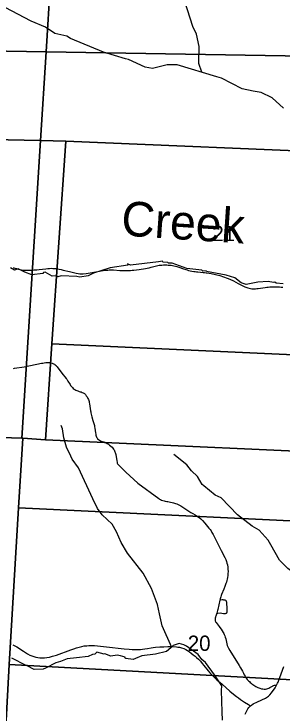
# Model space of a CAD drawing. Extents: x 0 to 34, y 0 to 22.
# Drawn here: x 25.024 to 25.758, y 15.745 to 17.66 of the extents above; entities that cross this region are included whole.
import ezdxf

# ---------------------------------------------------------------- set-up
doc = ezdxf.new("R2010")
doc.units = 0
for name, color, linetype in [('GM_X_County_Road', 7, 'Continuous'), ('GM_X_Minor_River', 7, 'Continuous'), ('GM_X_Minor_River_Text', 7, 'Continuous'), ('GM_X_Section', 7, 'Continuous'), ('GM_X_Section_Text', 7, 'Continuous'), ('GM_X_State_Route', 7, 'Continuous'), ('GM_X_Township_Road', 7, 'Continuous')]:
    doc.layers.add(name, color=color, linetype=linetype)

msp = doc.modelspace()

# ---------------------------------------------------------------- linework, layer by layer
at = {"layer": 'GM_X_County_Road'}
for points in [[(25.328, 16.9572), (25.333, 16.9571), (25.3432, 16.9573), (25.3478, 16.9576), (25.3525, 16.9581), (25.3671, 16.96), (25.3728, 16.9608), (25.3785, 16.9618), (25.3941, 16.9647), (25.3969, 16.9654), (25.4, 16.9662), (25.4145, 16.9699), (25.418, 16.9706), (25.4217, 16.9713), (25.4255, 16.9718), (25.4295, 16.9722), (25.4338, 16.9724), (25.4383, 16.9725), (25.4427, 16.9724), (25.4465, 16.9722), (25.4496, 16.9719), (25.4525, 16.9717), (25.455, 16.9713), (25.4579, 16.9707), (25.4623, 16.9697), (25.4663, 16.9688), (25.4701, 16.9677), (25.4752, 16.9661), (25.4886, 16.9616), (25.4945, 16.9597), (25.4983, 16.9586), (25.5023, 16.9575), (25.5067, 16.9565), (25.5109, 16.9556), (25.5168, 16.9546), (25.5203, 16.9541), (25.5238, 16.9536), (25.5278, 16.9532), (25.5419, 16.9521), (25.5462, 16.9517), (25.5501, 16.9512), (25.5535, 16.9506), (25.5638, 16.9488), (25.5757, 16.9462), (25.5878, 16.9432), (25.5983, 16.9399), (25.6079, 16.9364), (25.6156, 16.9333), (25.6249, 16.9291), (25.6315, 16.9256), (25.6382, 16.9219), (25.651, 16.915), (25.6563, 16.9124), (25.6616, 16.9104), (25.665, 16.9093), (25.6685, 16.9084), (25.6717, 16.9077), (25.6752, 16.9073), (25.6786, 16.9071), (25.682, 16.9071), (25.6858, 16.9072), (25.6893, 16.9074), (25.6924, 16.9078), (25.7123, 16.9108), (25.7163, 16.9114), (25.7203, 16.9118), (25.725, 16.9122), (25.7302, 16.9125), (25.7344, 16.9126), (25.7388, 16.9126), (25.7451, 16.9126), (25.7512, 16.9123), (25.7561, 16.9119), (25.7608, 16.9114)], [(25.0219, 16.9658), (25.0267, 16.9639), (25.0311, 16.9622), (25.0361, 16.9608), (25.0406, 16.9598), (25.0452, 16.959), (25.0501, 16.9585), (25.0559, 16.9582), (25.0608, 16.9581), (25.0659, 16.958), (25.0745, 16.9584), (25.0798, 16.9586), (25.0863, 16.9591), (25.0935, 16.9599), (25.1116, 16.9621), (25.1166, 16.9625), (25.1215, 16.9629), (25.1262, 16.9631), (25.1305, 16.963), (25.1356, 16.9627), (25.1398, 16.9623), (25.1439, 16.9617), (25.1481, 16.9609), (25.1532, 16.9598), (25.1587, 16.9585), (25.1766, 16.9541), (25.1946, 16.9497), (25.1998, 16.9487), (25.2045, 16.948), (25.2094, 16.9477), (25.214, 16.9479), (25.2214, 16.9485), (25.2272, 16.9494), (25.2486, 16.9533), (25.2683, 16.9571), (25.2714, 16.9576), (25.2743, 16.958), (25.2776, 16.9583), (25.2808, 16.9585), (25.2851, 16.9587), (25.2895, 16.9588), (25.2931, 16.9587), (25.2964, 16.9586), (25.3139, 16.9574), (25.328, 16.9572)], [(25.023, 16.689), (25.0254, 16.6893), (25.0524, 16.6936), (25.0994, 16.703), (25.1029, 16.7036), (25.1069, 16.7042), (25.1112, 16.7047), (25.1148, 16.705), (25.1183, 16.7051), (25.1217, 16.7048), (25.1251, 16.7042), (25.1286, 16.7031), (25.1321, 16.7018), (25.1349, 16.7005), (25.1371, 16.6991), (25.1393, 16.6973), (25.1409, 16.6954), (25.1426, 16.6932), (25.1555, 16.6762), (25.167, 16.6612), (25.1687, 16.6591), (25.1701, 16.6572), (25.172, 16.6543), (25.1777, 16.6446), (25.1792, 16.6424), (25.1806, 16.6405), (25.184, 16.6363), (25.1862, 16.6341), (25.1886, 16.6321), (25.1908, 16.6307), (25.1934, 16.6292), (25.1961, 16.628), (25.1989, 16.6271), (25.2024, 16.626), (25.2052, 16.6252), (25.2081, 16.6243), (25.211, 16.6232), (25.2138, 16.6219), (25.2169, 16.6198), (25.2196, 16.6174), (25.2223, 16.6141), (25.2243, 16.6111), (25.2266, 16.6067), (25.2279, 16.604), (25.2289, 16.6014), (25.2299, 16.5982), (25.2305, 16.5955), (25.231, 16.5921), (25.2339, 16.5724), (25.2343, 16.5698), (25.2347, 16.5672), (25.2365, 16.5595), (25.2374, 16.556), (25.2402, 16.546), (25.2429, 16.5377), (25.2436, 16.5352), (25.2443, 16.5322), (25.245, 16.529), (25.2455, 16.5254), (25.2473, 16.5126), (25.2479, 16.5087), (25.2487, 16.5057), (25.2494, 16.5032), (25.2504, 16.5008), (25.2516, 16.4985), (25.2532, 16.4961), (25.2554, 16.4939), (25.258, 16.4921), (25.2615, 16.4905), (25.2653, 16.4891), (25.2698, 16.4877), (25.2734, 16.4865), (25.2767, 16.4851), (25.2798, 16.4834), (25.2827, 16.4814), (25.2856, 16.4791), (25.2896, 16.4758), (25.2926, 16.473), (25.2949, 16.4704), (25.2967, 16.468), (25.2984, 16.4655), (25.2997, 16.463), (25.3007, 16.4607), (25.3015, 16.4583), (25.3021, 16.4558), (25.3027, 16.4528), (25.3055, 16.4361), (25.3063, 16.4324), (25.307, 16.4297), (25.3081, 16.4276), (25.3095, 16.4255), (25.3127, 16.4224), (25.3305, 16.4045), (25.3637, 16.3749), (25.4208, 16.3326), (25.423, 16.3311), (25.4253, 16.3297), (25.4281, 16.3283), (25.4314, 16.327), (25.435, 16.3259), (25.4386, 16.3252), (25.4427, 16.3245), (25.4456, 16.324), (25.449, 16.3236), (25.4528, 16.3229), (25.457, 16.322), (25.4606, 16.321), (25.4638, 16.32), (25.4669, 16.3189), (25.47, 16.3176), (25.4737, 16.3161), (25.4771, 16.3144), (25.4807, 16.3125), (25.4842, 16.3104), (25.4977, 16.3011), (25.5034, 16.2974), (25.5086, 16.2942), (25.514, 16.2911), (25.5201, 16.2878), (25.5269, 16.2836), (25.5314, 16.2803), (25.5356, 16.2767), (25.54, 16.2724), (25.5467, 16.2651), (25.5581, 16.2517), (25.5615, 16.2474), (25.564, 16.2438), (25.5664, 16.2397), (25.5694, 16.2343), (25.5725, 16.2287), (25.5913, 16.19), (25.6014, 16.1707), (25.6039, 16.1652), (25.6061, 16.1598), (25.6075, 16.1553), (25.6086, 16.1506), (25.6096, 16.1447), (25.6101, 16.1394), (25.6103, 16.1328), (25.6101, 16.1272), (25.6096, 16.1217), (25.6087, 16.1164), (25.6079, 16.112), (25.6069, 16.1077), (25.6058, 16.1036), (25.6047, 16.1001), (25.6019, 16.0919), (25.5988, 16.0842), (25.5929, 16.0696), (25.5917, 16.0665), (25.5905, 16.0629), (25.5895, 16.0601), (25.5887, 16.0574), (25.5879, 16.0543)], [(25.5879, 16.0543), (25.5852, 16.0417), (25.5824, 16.0284), (25.5817, 16.0253), (25.5808, 16.0221), (25.5794, 16.0181), (25.5765, 16.01), (25.5761, 16.0084), (25.5756, 16.0068), (25.5753, 16.0056), (25.5751, 16.0044), (25.575, 16.0029), (25.5749, 16.0015), (25.575, 16), (25.5751, 15.9985), (25.5753, 15.997), (25.5757, 15.9958), (25.5762, 15.9944), (25.5774, 15.9927), (25.5803, 15.9888), (25.5859, 15.9816), (25.5882, 15.9787), (25.5911, 15.9746), (25.5946, 15.9698), (25.5974, 15.965), (25.5988, 15.9625), (25.6001, 15.9596), (25.6013, 15.9564), (25.6026, 15.9524), (25.6041, 15.9477), (25.605, 15.9436), (25.606, 15.9389), (25.607, 15.9344), (25.6082, 15.93), (25.6098, 15.9262), (25.6119, 15.9222), (25.6154, 15.9162), (25.6405, 15.8751), (25.6443, 15.8688), (25.6496, 15.8593), (25.6523, 15.8543), (25.6547, 15.8498), (25.6571, 15.8459), (25.6592, 15.8424), (25.6611, 15.8397), (25.6631, 15.837), (25.665, 15.8348), (25.6668, 15.8328), (25.6688, 15.8309), (25.6709, 15.8289), (25.6733, 15.827), (25.6758, 15.825), (25.6784, 15.8231), (25.6814, 15.8211), (25.6839, 15.8195), (25.6868, 15.8178), (25.6923, 15.815), (25.6947, 15.8139), (25.6975, 15.8128), (25.7017, 15.8115), (25.7055, 15.8108), (25.7093, 15.8105), (25.7131, 15.8106), (25.7168, 15.8113), (25.7192, 15.812), (25.7224, 15.8134), (25.7251, 15.8148), (25.7318, 15.8187), (25.7331, 15.8195), (25.7346, 15.8202), (25.7362, 15.8207), (25.7377, 15.8211), (25.7396, 15.8212), (25.743, 15.8212)], [(25.021, 15.9314), (25.0266, 15.9289), (25.0318, 15.9261), (25.0365, 15.9231), (25.0428, 15.919), (25.0507, 15.914), (25.0613, 15.9073), (25.0679, 15.9038), (25.0731, 15.9016), (25.0785, 15.8997), (25.0839, 15.8983), (25.0893, 15.8971), (25.0952, 15.8963), (25.1011, 15.8959), (25.1073, 15.8961), (25.1138, 15.8968), (25.121, 15.8983), (25.13, 15.9004), (25.1403, 15.9034), (25.1799, 15.9178), (25.188, 15.9208), (25.195, 15.9232), (25.2027, 15.9254), (25.21, 15.9273), (25.2168, 15.9285), (25.2238, 15.9293), (25.2291, 15.9297), (25.2349, 15.9299), (25.2395, 15.9299), (25.2448, 15.9296), (25.2528, 15.9289), (25.2776, 15.9259), (25.3261, 15.9208), (25.3398, 15.9195), (25.3478, 15.9189), (25.3541, 15.9188), (25.3605, 15.9188), (25.3654, 15.9189), (25.3705, 15.9192), (25.3759, 15.9197), (25.3821, 15.9206), (25.3901, 15.9217), (25.3995, 15.9233), (25.4057, 15.9243), (25.412, 15.9251), (25.4239, 15.9259), (25.4347, 15.9265), (25.4459, 15.9267), (25.4583, 15.9267), (25.4688, 15.9262), (25.4731, 15.9257), (25.4775, 15.925), (25.4833, 15.9235), (25.4892, 15.9212), (25.4946, 15.9186), (25.4994, 15.9158), (25.5046, 15.9125), (25.5095, 15.909), (25.515, 15.9047), (25.5199, 15.9006), (25.5243, 15.8967), (25.5291, 15.8921), (25.5345, 15.8865), (25.5399, 15.8804), (25.544, 15.8754), (25.5478, 15.8706), (25.5522, 15.865), (25.5559, 15.8606), (25.5605, 15.8552), (25.5667, 15.8486), (25.572, 15.8431), (25.5798, 15.836), (25.5942, 15.8235), (25.6153, 15.8049), (25.6297, 15.7929), (25.6336, 15.7898), (25.6386, 15.7861), (25.6448, 15.7819), (25.6551, 15.7747), (25.666, 15.7679), (25.6718, 15.7643)]]:
    msp.add_lwpolyline(points, dxfattribs=at)
at = {"layer": 'GM_X_Minor_River'}
for points in [[(25.5382, 17.5003), (25.5308, 17.5239), (25.5311, 17.5706), (25.5238, 17.605), (25.5135, 17.6258), (25.4835, 17.7209), (25.4705, 17.7415), (25.4521, 17.7595), (25.4033, 17.7956), (25.3784, 17.8078), (25.3491, 17.8281), (25.3231, 17.854), (25.2605, 17.8969), (25.2384, 17.9166), (25.1927, 17.9671)], [(25.7618, 17.4019), (25.7313, 17.4298), (25.7011, 17.4452), (25.6793, 17.4486), (25.6489, 17.4545), (25.5923, 17.484), (25.58, 17.4878), (25.4706, 17.5205), (25.4434, 17.5202), (25.4034, 17.5104), (25.3831, 17.5145), (25.3376, 17.5349), (25.3297, 17.5371), (25.2694, 17.5549), (25.1787, 17.5931), (25.1691, 17.5991), (25.1361, 17.6066), (25.1105, 17.6234), (25.0709, 17.6406), (24.9474, 17.706)], [(25.7612, 16.9206), (25.7423, 16.9221), (25.7385, 16.9251), (25.7348, 16.9247), (25.72, 16.927), (25.6921, 16.925), (25.6603, 16.9188), (25.6463, 16.923), (25.6285, 16.9366), (25.6055, 16.9445), (25.5518, 16.9543), (25.5503, 16.9565), (25.5416, 16.955), (25.5382, 16.958), (25.4977, 16.9629), (25.4569, 16.9772), (25.4471, 16.9772), (25.4455, 16.9795), (25.4319, 16.9802), (25.4308, 16.9825), (25.4198, 16.9805), (25.3435, 16.972), (25.3352, 16.975), (25.3359, 16.9719), (25.2872, 16.9642), (25.2422, 16.95), (25.2271, 16.9424), (25.2044, 16.9393), (25.1961, 16.9408), (25.1538, 16.9422), (25.1439, 16.9399), (25.1401, 16.9429), (25.1284, 16.9418), (25.1095, 16.9524), (25.1046, 16.9516), (25.1031, 16.9489), (25.0729, 16.9454), (25.0539, 16.9522), (25.0358, 16.9613), (25.0256, 16.9579), (25.0146, 16.9647)], [(25.4563, 15.9246), (25.4298, 15.9839), (25.4228, 16.0164), (25.4168, 16.0421), (25.4008, 16.0862), (25.3775, 16.128), (25.3349, 16.1832), (25.3173, 16.2119), (25.3053, 16.2411), (25.2931, 16.262), (25.2655, 16.288), (25.2528, 16.3051), (25.24, 16.3313), (25.2006, 16.4161), (25.1836, 16.4401), (25.1801, 16.4482), (25.1676, 16.4733), (25.1604, 16.4986), (25.1574, 16.5237), (25.1531, 16.5322)], [(25.8517, 15.9199), (25.8493, 15.9401), (25.8395, 15.9769), (25.8416, 15.9977), (25.8398, 16.0125), (25.8152, 16.0987), (25.8052, 16.1177), (25.7738, 16.1407), (25.751, 16.1638), (25.7277, 16.2055), (25.7205, 16.2183), (25.6953, 16.2461), (25.676, 16.2569), (25.6365, 16.2878), (25.5914, 16.334), (25.575, 16.3421), (25.5444, 16.3674), (25.5396, 16.3713), (25.527, 16.3926), (25.5105, 16.4079), (25.4978, 16.4251), (25.462, 16.4531)], [(25.5949, 15.7253), (25.5941, 15.7481), (25.5925, 15.8066), (25.5936, 15.8192), (25.5736, 15.8495), (25.5486, 15.8833), (25.5384, 15.8913), (25.5282, 15.9053), (25.4968, 15.9284), (25.4896, 15.9318), (25.4767, 15.9352), (25.4605, 15.9294), (25.4537, 15.923), (25.4416, 15.9138), (25.4121, 15.9058), (25.3743, 15.9019), (25.3566, 15.8938), (25.3509, 15.8915), (25.3309, 15.8945), (25.3278, 15.8957), (25.329, 15.8976), (25.3161, 15.9013), (25.3063, 15.9032), (25.2897, 15.9005), (25.2734, 15.9073), (25.2711, 15.9062), (25.2507, 15.9118), (25.2454, 15.9061), (25.2394, 15.9053), (25.2277, 15.8996), (25.1955, 15.8965), (25.1695, 15.893), (25.1513, 15.8857), (25.1385, 15.8826), (25.1101, 15.8681), (25.1045, 15.8647), (25.0791, 15.8643), (25.0606, 15.8737), (25.058, 15.8752), (25.0182, 15.8949)]]:
    msp.add_lwpolyline(points, dxfattribs=at)
at = {"layer": 'GM_X_Section'}
for points in [[(24.0951, 17.7788), (25.1245, 17.7506), (25.1122, 17.5559), (24.0818, 17.5731)], [(25.1245, 17.7506), (26.1578, 17.7173), (26.1482, 17.5386), (25.1122, 17.5559)], [(24.0815, 17.5702), (24.0818, 17.5731), (25.1122, 17.5559), (25.097, 17.3132), (24.6087, 17.3232), (24.0677, 17.3343)], [(26.1482, 17.5386), (26.1481, 17.5351), (26.131, 17.2706), (25.9484, 17.2784), (25.1664, 17.3116), (25.097, 17.3132), (25.1122, 17.5559)], [(25.097, 17.3132), (25.0459, 16.4982), (24.5596, 16.5135), (24.6087, 17.3232)], [(25.1664, 17.3116), (25.1282, 16.7564), (25.1102, 16.4936), (25.0486, 16.498), (25.0459, 16.4982), (25.097, 17.3132)], [(25.9484, 17.2784), (25.9113, 16.7209), (25.1282, 16.7564), (25.1664, 17.3116)], [(25.1282, 16.7564), (25.9113, 16.7209), (26.0957, 16.7125), (26.0791, 16.4497), (25.1102, 16.4936)], [(24.5596, 16.5135), (25.0459, 16.4982), (25.0486, 16.498), (25.0369, 16.3074), (25.0112, 15.8778), (24.9883, 15.4512), (23.9474, 15.5054), (24.0115, 16.5331)], [(25.1102, 16.4936), (26.0791, 16.4497), (26.067, 16.2576), (25.0369, 16.3074), (25.0486, 16.498)], [(25.0369, 16.3074), (26.067, 16.2576), (26.0395, 15.8225), (25.0112, 15.8778)], [(26.0395, 15.8225), (26.0137, 15.3999), (24.9883, 15.4512), (25.0112, 15.8778)]]:
    msp.add_lwpolyline(points, close=True, dxfattribs=at)
at = {"layer": 'GM_X_State_Route'}
for points in [[(25.6794, 15.7697), (25.6831, 15.7719), (25.687, 15.7739), (25.6908, 15.7757), (25.7127, 15.7854), (25.7159, 15.7872), (25.7186, 15.789), (25.7208, 15.7907), (25.7231, 15.7928), (25.7252, 15.7949), (25.7291, 15.7998), (25.739, 15.8141), (25.743, 15.8212), (25.7462, 15.8271), (25.7475, 15.8298), (25.7486, 15.8324), (25.7632, 15.8724)], [(25.6577, 15.7421), (25.6598, 15.7475), (25.6624, 15.7526), (25.6646, 15.7561), (25.6677, 15.7602), (25.6711, 15.7637), (25.6718, 15.7643), (25.6749, 15.7667), (25.6794, 15.7697)]]:
    msp.add_lwpolyline(points, dxfattribs=at)
at = {"layer": 'GM_X_Township_Road'}
msp.add_lwpolyline([(25.5794, 16.0181), (25.5814, 16.0183), (25.5828, 16.0184), (25.5884, 16.0191), (25.5981, 16.0175), (25.5995, 16.0173), (25.6012, 16.0173), (25.6024, 16.0174), (25.6036, 16.0176), (25.6048, 16.018), (25.6059, 16.0187), (25.6069, 16.0196), (25.6074, 16.0204), (25.6078, 16.0215), (25.608, 16.0228), (25.6076, 16.0326), (25.607, 16.045), (25.6068, 16.0468), (25.6067, 16.0483), (25.6064, 16.0495), (25.606, 16.0507), (25.6057, 16.0515), (25.6053, 16.0522), (25.6046, 16.0529), (25.6039, 16.0533), (25.6029, 16.0537), (25.6018, 16.0539), (25.6004, 16.0542), (25.5989, 16.0543), (25.5968, 16.0545), (25.5946, 16.0545), (25.5879, 16.0543)], dxfattribs=at)

# ---------------------------------------------------------------- texts
at = {"layer": 'GM_X_Minor_River_Text'}
msp.add_text('Creek', height=0.09469, rotation=356.1515, dxfattribs=at).set_placement((25.3159, 17.0535))
at = {"layer": 'GM_X_Section_Text'}
for s, p in [('21', (25.5676, 17.0375)), ('20', (25.5001, 15.9151))]:
    msp.add_text(s, height=0.04186, rotation=0, dxfattribs=at).set_placement(p)

doc.saveas('drawing.dxf')
